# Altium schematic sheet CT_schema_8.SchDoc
size 277 x 170 mm
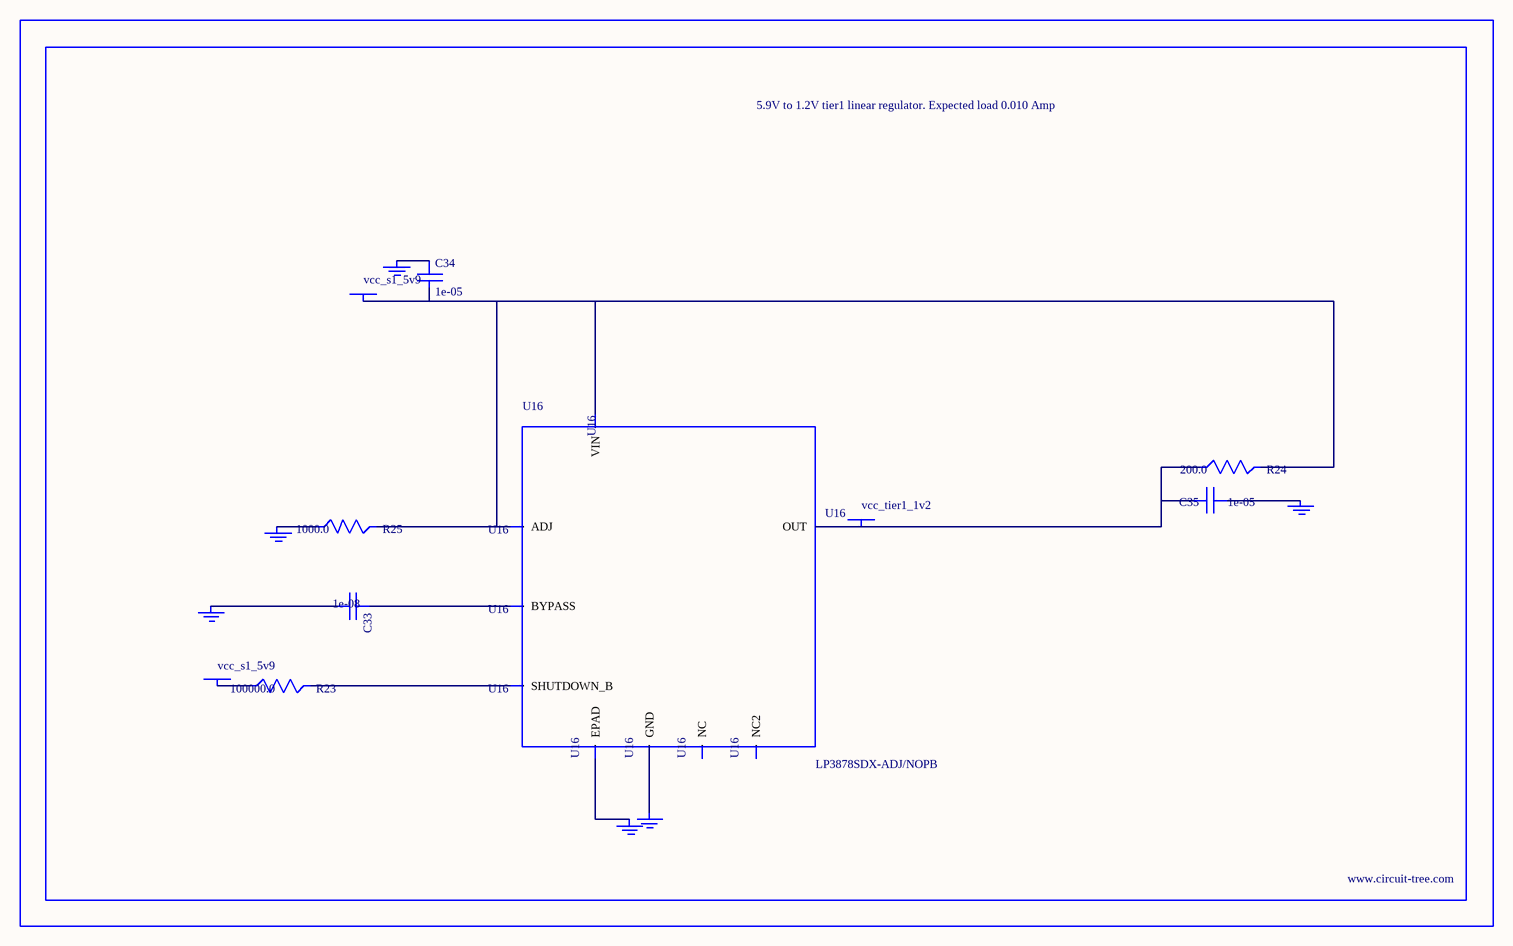
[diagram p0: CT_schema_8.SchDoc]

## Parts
BORDER7  (no value)
C33  1e-08  [C0402]
C34  1e-05  [C1206]
C35  1e-05  [C0805]
GND_INSTANCE_7_0  (no value)
GND_INSTANCE_7_1  (no value)
GND_INSTANCE_7_2  (no value)
GND_INSTANCE_7_3  (no value)
GND_INSTANCE_7_4  (no value)
GND_INSTANCE_7_5  (no value)
POWER_INSTANCE_7_0  vcc_s1_5v9
POWER_INSTANCE_7_1  vcc_s1_5v9
POWER_INSTANCE_7_2  vcc_tier1_1v2
R23  100000.0  [R0603]
R24  200.0  [R0603]
R25  1000.0  [R0603]
U16  LP3878SDX-ADJ/NOPB  [WSON-8]

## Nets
NetC33_1: C33.1 U16.1(BYPASS)
NetC33_2: C33.2 GND_INSTANCE_7_0.0(GND)
NetC34_1: C34.1 GND_INSTANCE_7_1.0(GND)
NetC34_2: C34.2 POWER_INSTANCE_7_0.0(PWR) R24.2 R25.2 U16.4(VIN) U16.6(ADJ)
NetC35_1: C35.1 GND_INSTANCE_7_2.0(GND)
NetC35_2: C35.2 POWER_INSTANCE_7_2.0(PWR) R24.1 U16.5(OUT)
NetGND_INSTANCE_7_3_0: GND_INSTANCE_7_3.0(GND) R25.1
NetGND_INSTANCE_7_4_0: GND_INSTANCE_7_4.0(GND) U16.PAD(EPAD)
NetGND_INSTANCE_7_5_0: GND_INSTANCE_7_5.0(GND) U16.3(GND)
NetPOWER_INSTANCE_7_1_0: POWER_INSTANCE_7_1.0(PWR) R23.1
NetR23_2: R23.2 U16.8(SHUTDOWN_B)

Not connected (* = marked no-connect by the designer): U16 2(NC) 7(NC2)

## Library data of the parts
BORDER7 = BORDER_PAGE7
C33 = C0402C103K3RAC
C34 = C1206C106K3RACTU
C35 = GRM219R60J106ME19D
GND_INSTANCE_7_0-GND_INSTANCE_7_5 = GND
POWER_INSTANCE_7_0-POWER_INSTANCE_7_2 = PWR
R23 = RC0603JR-07100KL
R24 = RC0603JR-07200RL
R25 = RC0603JR-071KL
